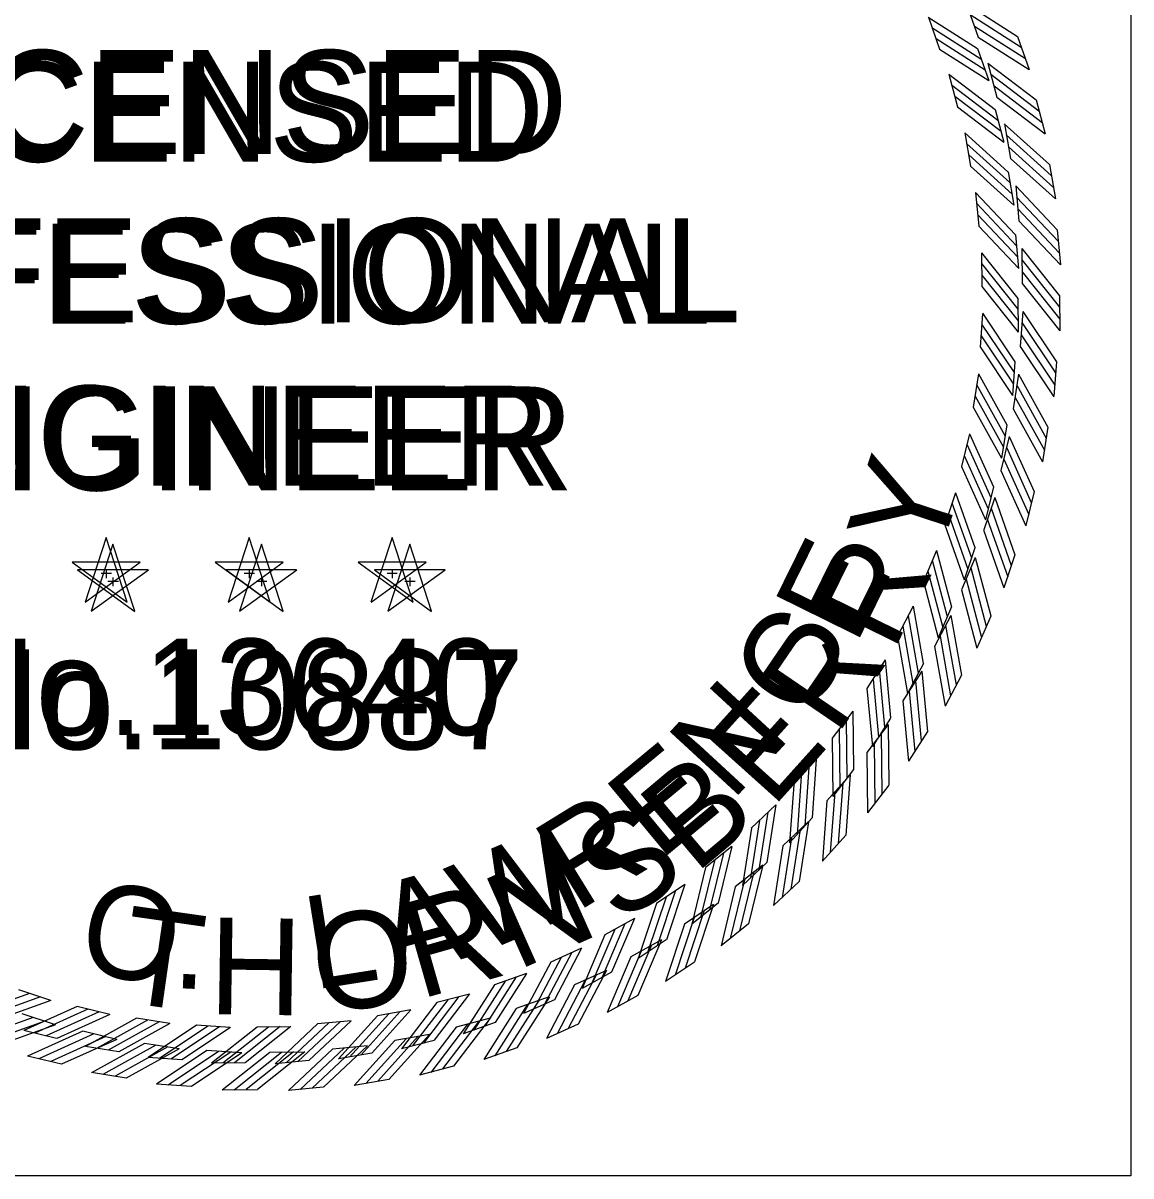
# Model space of a CAD drawing. Extents: x 0 to 1228740, y 0 to 152440.
# Drawn here: x 35.691 to 37.414, y 22.317 to 24.11 of the extents above; entities that cross this region are included whole.
import ezdxf

# ---------------------------------------------------------------- set-up
doc = ezdxf.new("R2010")
doc.units = 0
for name, color, linetype in [('R_No Plot', 7, 'Continuous'), ('STAMP', 7, 'Continuous'), ('STAMP_PP', 7, 'Continuous')]:
    doc.layers.add(name, color=color, linetype=linetype)

msp = doc.modelspace()

# ---------------------------------------------------------------- linework, layer by layer
at = {"layer": 'R_No Plot'}
msp.add_lwpolyline([(34.6722, 25.0583), (37.4139, 25.0583), (37.4139, 22.3166), (34.6722, 22.3166)], close=True, dxfattribs=at)
at = {"layer": 'STAMP'}
for p, q in [((37.0989, 24.1186), (37.1164, 24.0691)), ((37.1753, 24.0698), (37.1928, 24.0204)), ((37.1309, 24.0299), (37.1443, 23.9791)), ((37.203, 23.9749), (37.2164, 23.9243)), ((37.1555, 23.9389), (37.1646, 23.8872)), ((37.2228, 23.8782), (37.2319, 23.8266)), ((37.1724, 23.8462), (37.1773, 23.7939)), ((37.2345, 23.7801), (37.2393, 23.7279)), ((37.1817, 23.7524), (37.1822, 23.6998)), ((37.2381, 23.6814), (37.2386, 23.629)), ((37.1832, 23.6581), (37.1793, 23.6057)), ((37.2335, 23.5827), (37.2297, 23.5304)), ((37.1768, 23.564), (37.1687, 23.5122)), ((37.1628, 23.4708), (37.1503, 23.4198)), ((37.2208, 23.4847), (37.2126, 23.433)), ((37.2, 23.3882), (37.1876, 23.3372)), ((37.1411, 23.3791), (37.1245, 23.3293)), ((35.8206, 23.3094), (35.7878, 23.2088)), ((35.8532, 23.2089), (35.8206, 23.3095)), ((36.0429, 23.3094), (36.0101, 23.2088)), ((36.0755, 23.2089), (36.0429, 23.3095)), ((36.2651, 23.3094), (36.2323, 23.2088)), ((36.2978, 23.2089), (36.2652, 23.3095)), ((37.1714, 23.2936), (37.1548, 23.2439)), ((37.1118, 23.2895), (37.0912, 23.2412)), ((35.8734, 23.271), (35.7676, 23.2711)), ((35.7677, 23.271), (35.8533, 23.2087)), ((35.7879, 23.2089), (35.8736, 23.271)), ((35.8207, 23.2598), (35.8207, 23.2465)), ((36.0957, 23.271), (35.9899, 23.2711)), ((35.99, 23.271), (36.0755, 23.2087)), ((36.0102, 23.2089), (36.0958, 23.271)), ((36.043, 23.2598), (36.043, 23.2465)), ((36.318, 23.271), (36.2122, 23.2711)), ((36.2123, 23.271), (36.2978, 23.2087)), ((36.2325, 23.2089), (36.3181, 23.271)), ((36.2652, 23.2598), (36.2652, 23.2465)), ((35.813, 23.2541), (35.8288, 23.2541)), ((36.0353, 23.2541), (36.051, 23.2541)), ((36.2576, 23.2541), (36.2733, 23.2541)), ((37.0753, 23.2026), (37.0508, 23.1561)), ((37.135, 23.2018), (37.1144, 23.1536)), ((37.0318, 23.119), (37.0034, 23.0747)), ((37.0912, 23.1133), (37.0666, 23.067)), ((36.9814, 23.0393), (36.9496, 22.9975)), ((37.0402, 23.0287), (37.0119, 22.9845)), ((36.9247, 22.964), (36.8895, 22.925)), ((36.9823, 22.9486), (36.9505, 22.9069)), ((36.8619, 22.8936), (36.8236, 22.8577)), ((36.9181, 22.8735), (36.883, 22.8346)), ((36.7936, 22.8287), (36.7524, 22.7961)), ((36.8479, 22.804), (36.8097, 22.7682)), ((36.7201, 22.7697), (36.6764, 22.7405)), ((36.7722, 22.7406), (36.7312, 22.708)), ((36.642, 22.7169), (36.596, 22.6914)), ((36.6915, 22.6836), (36.6479, 22.6545)), ((36.5598, 22.6707), (36.5119, 22.6492)), ((36.4741, 22.6315), (36.4246, 22.614)), ((36.6064, 22.6335), (36.5606, 22.6081)), ((35.7346, 22.5894), (35.6848, 22.606)), ((36.3854, 22.5995), (36.3346, 22.5861)), ((35.8263, 22.5676), (35.7753, 22.5801)), ((36.2944, 22.5749), (36.2427, 22.5658)), ((36.5175, 22.5905), (36.4697, 22.569)), ((35.9195, 22.5536), (35.8676, 22.5617)), ((36.2017, 22.558), (36.1494, 22.5532)), ((35.7436, 22.5304), (35.6927, 22.5428)), ((36.0136, 22.5473), (35.9612, 22.5511)), ((36.1078, 22.5487), (36.0553, 22.5482)), ((36.4252, 22.5551), (36.3758, 22.5376)), ((36.3304, 22.5274), (36.2798, 22.5141)), ((35.8402, 22.5096), (35.7885, 22.5178)), ((36.2337, 22.5076), (36.182, 22.4985)), ((35.9382, 22.4969), (35.8859, 22.5007)), ((36.0369, 22.4923), (35.9845, 22.4918)), ((36.1356, 22.4959), (36.0834, 22.4911))]:
    msp.add_line(p, q, dxfattribs=at)
for points in [[(37.0988, 24.1186), (37.1753, 24.0698)], [(37.1043, 24.1027), (37.1807, 24.0539)], [(37.1108, 24.0857), (37.1872, 24.0368)], [(37.1164, 24.0691), (37.1928, 24.0203)], [(37.1308, 24.03), (37.203, 23.975)], [(37.135, 24.0136), (37.2071, 23.9587)], [(37.14, 23.9961), (37.2121, 23.9412)], [(37.1443, 23.9792), (37.2164, 23.9242)], [(37.1554, 23.939), (37.2227, 23.8782)], [(37.1582, 23.9223), (37.2255, 23.8616)], [(37.1617, 23.9045), (37.2291, 23.8437)], [(37.1646, 23.8872), (37.232, 23.8265)], [(37.1724, 23.8462), (37.2345, 23.7802)], [(37.1738, 23.8294), (37.2359, 23.7633)], [(37.1758, 23.8113), (37.2379, 23.7453)], [(37.1773, 23.7939), (37.2394, 23.7279)], [(37.1816, 23.7524), (37.2381, 23.6814)], [(37.1816, 23.7356), (37.2381, 23.6646)], [(37.1822, 23.7174), (37.2386, 23.6464)], [(37.1822, 23.6999), (37.2386, 23.6289)], [(37.1831, 23.6582), (37.2335, 23.5828)], [(37.1817, 23.6414), (37.2321, 23.566)], [(37.1808, 23.6232), (37.2311, 23.5478)], [(37.1793, 23.6058), (37.2297, 23.5304)], [(37.1768, 23.5641), (37.2208, 23.4848)], [(37.174, 23.5475), (37.218, 23.4682)], [(37.1716, 23.5294), (37.2156, 23.4501)], [(37.1687, 23.5122), (37.2127, 23.4329)], [(37.1627, 23.4709), (37.2, 23.3882)], [(37.1586, 23.4546), (37.1959, 23.3719)], [(37.1547, 23.4368), (37.1919, 23.3541)], [(37.1504, 23.4198), (37.1877, 23.3372)], [(37.1356, 23.3632), (37.1659, 23.2778)], [(37.141, 23.3792), (37.1713, 23.2937)], [(37.1302, 23.3458), (37.1605, 23.2604)], [(37.1245, 23.3293), (37.1548, 23.2439)], [(37.105, 23.2741), (37.1282, 23.1864)], [(37.1118, 23.2895), (37.135, 23.2019)], [(37.0983, 23.2572), (37.1214, 23.1695)], [(37.0912, 23.2412), (37.1144, 23.1536)], [(37.0753, 23.2026), (37.0911, 23.1134)], [(37.0673, 23.1878), (37.0831, 23.0985)], [(37.0591, 23.1715), (37.075, 23.0823)], [(37.0508, 23.1562), (37.0666, 23.0669)], [(37.0317, 23.119), (37.0402, 23.0288)], [(37.0225, 23.1049), (37.0309, 23.0146)], [(37.013, 23.0894), (37.0215, 22.9991)], [(37.0035, 23.0748), (37.0119, 22.9845)], [(36.9711, 23.026), (36.972, 22.9354)], [(36.9814, 23.0393), (36.9824, 22.9487)], [(36.9603, 23.0113), (36.9613, 22.9206)], [(36.9496, 22.9975), (36.9505, 22.9069)], [(36.9133, 22.9516), (36.9067, 22.8612)], [(36.9247, 22.964), (36.9181, 22.8736)], [(36.9014, 22.9379), (36.8948, 22.8474)], [(36.8896, 22.925), (36.883, 22.8346)], [(36.8495, 22.8823), (36.8355, 22.7927)], [(36.862, 22.8937), (36.8479, 22.8041)], [(36.8365, 22.8695), (36.8225, 22.78)], [(36.8237, 22.8577), (36.8097, 22.7681)], [(36.7936, 22.8288), (36.7722, 22.7407)], [(36.7803, 22.8184), (36.7589, 22.7303)], [(36.7525, 22.7961), (36.7311, 22.708)], [(36.7663, 22.8068), (36.7449, 22.7187)], [(36.706, 22.7605), (36.6774, 22.6744)], [(36.7201, 22.7697), (36.6916, 22.6837)], [(36.6765, 22.7405), (36.6479, 22.6545)], [(36.6911, 22.7501), (36.6625, 22.664)], [(36.6115, 22.6997), (36.5759, 22.6163)], [(36.6272, 22.7089), (36.5916, 22.6255)], [(36.642, 22.7169), (36.6065, 22.6335)], [(36.5961, 22.6914), (36.5605, 22.608)], [(36.5444, 22.664), (36.5021, 22.5838)], [(36.5598, 22.6708), (36.5175, 22.5906)], [(36.512, 22.6492), (36.4696, 22.569)], [(36.528, 22.6562), (36.4856, 22.576)], [(36.4741, 22.6316), (36.4253, 22.5552)], [(36.4246, 22.614), (36.3758, 22.5376)], [(36.4411, 22.6196), (36.3923, 22.5432)], [(36.4582, 22.6261), (36.4094, 22.5497)], [(35.7013, 22.6002), (35.6159, 22.5699)], [(35.7187, 22.5949), (35.6333, 22.5645)], [(36.3691, 22.5954), (36.3141, 22.5233)], [(36.3855, 22.5996), (36.3305, 22.5275)], [(35.7347, 22.5894), (35.6492, 22.5591)], [(35.7753, 22.58), (35.6927, 22.5428)], [(35.7923, 22.5757), (35.7096, 22.5385)], [(36.2944, 22.575), (36.2337, 22.5077)], [(36.3347, 22.5861), (36.2797, 22.514)], [(36.3516, 22.5904), (36.2966, 22.5183)], [(35.81, 22.5718), (35.7274, 22.5346)], [(35.8264, 22.5677), (35.7437, 22.5304)], [(35.8677, 22.5617), (35.7884, 22.5177)], [(35.8849, 22.5588), (35.8056, 22.5149)], [(35.903, 22.5564), (35.8237, 22.5124)], [(36.1849, 22.5566), (36.1188, 22.4946)], [(36.2017, 22.558), (36.1356, 22.4959)], [(36.2427, 22.5658), (36.182, 22.4985)], [(36.26, 22.5687), (36.1992, 22.5013)], [(36.2778, 22.5722), (36.2171, 22.5049)], [(35.9196, 22.5536), (35.8403, 22.5097)], [(35.9613, 22.5511), (35.8859, 22.5007)], [(35.9787, 22.5496), (35.9033, 22.4993)], [(35.9968, 22.5487), (35.9214, 22.4983)], [(36.0137, 22.5473), (35.9383, 22.4969)], [(36.0554, 22.5482), (35.9844, 22.4918)], [(36.0728, 22.5482), (36.0019, 22.4918)], [(36.091, 22.5488), (36.0201, 22.4924)], [(36.1079, 22.5488), (36.0369, 22.4924)], [(36.1494, 22.5531), (36.0833, 22.491)], [(36.1668, 22.5546), (36.1007, 22.4925)]]:
    msp.add_lwpolyline(points, dxfattribs=at)
at = {"layer": 'STAMP_PP'}
for p, q in [((37.1584, 24.1392), (37.1766, 24.0878)), ((37.2377, 24.0885), (37.2559, 24.0372)), ((37.1916, 24.0472), (37.2055, 23.9944)), ((37.2665, 23.9901), (37.2803, 23.9375)), ((37.2171, 23.9527), (37.2266, 23.899)), ((37.287, 23.8896), (37.2965, 23.836)), ((37.2347, 23.8564), (37.2397, 23.8021)), ((37.2992, 23.7878), (37.3042, 23.7336)), ((37.2443, 23.759), (37.2448, 23.7045)), ((37.3029, 23.6853), (37.3034, 23.6309)), ((37.2459, 23.6611), (37.2418, 23.6067)), ((37.2981, 23.5828), (37.2941, 23.5286)), ((37.2393, 23.5635), (37.2308, 23.5096)), ((37.2849, 23.4811), (37.2765, 23.4274)), ((37.2247, 23.4667), (37.2118, 23.4137)), ((37.2021, 23.3715), (37.1849, 23.3197)), ((37.2634, 23.3809), (37.2505, 23.328)), ((35.8311, 23.2991), (35.7971, 23.1947)), ((35.8651, 23.1947), (35.8312, 23.2992)), ((36.0619, 23.2991), (36.0279, 23.1947)), ((36.0958, 23.1947), (36.062, 23.2992)), ((36.2927, 23.2991), (36.2587, 23.1947)), ((36.3266, 23.1947), (36.2928, 23.2992)), ((37.1718, 23.2784), (37.1504, 23.2283)), ((37.2336, 23.2827), (37.2164, 23.2311)), ((35.886, 23.2592), (35.7762, 23.2593)), ((35.7763, 23.2592), (35.8651, 23.1946)), ((35.7972, 23.1947), (35.8862, 23.2592)), ((36.1168, 23.2592), (36.007, 23.2593)), ((36.0071, 23.2592), (36.0959, 23.1946)), ((36.028, 23.1947), (36.1169, 23.2592)), ((36.3476, 23.2592), (36.2377, 23.2593)), ((36.2378, 23.2592), (36.3266, 23.1946)), ((36.2588, 23.1947), (36.3477, 23.2592)), ((35.8233, 23.2417), (35.8397, 23.2417)), ((35.8312, 23.2475), (35.8312, 23.2338)), ((36.0541, 23.2417), (36.0704, 23.2417)), ((36.062, 23.2475), (36.062, 23.2338)), ((36.2849, 23.2417), (36.3012, 23.2417)), ((36.2928, 23.2475), (36.2928, 23.2338)), ((37.1339, 23.1882), (37.1084, 23.14)), ((37.1958, 23.1874), (37.1744, 23.1373)), ((37.0887, 23.1014), (37.0593, 23.0554)), ((37.1503, 23.0955), (37.1249, 23.0474)), ((37.0364, 23.0186), (37.0033, 22.9753)), ((37.0974, 23.0076), (37.068, 22.9618)), ((36.9775, 22.9404), (36.9409, 22.9)), ((37.0374, 22.9245), (37.0043, 22.8812)), ((36.9123, 22.8674), (36.8726, 22.8301)), ((36.9707, 22.8465), (36.9342, 22.8062)), ((36.8414, 22.8), (36.7987, 22.7661)), ((36.8978, 22.7744), (36.8581, 22.7372)), ((36.7651, 22.7387), (36.7197, 22.7084)), ((36.8192, 22.7085), (36.7766, 22.6747)), ((36.684, 22.6839), (36.6363, 22.6575)), ((36.7354, 22.6493), (36.6901, 22.6192)), ((36.5987, 22.636), (36.5489, 22.6136)), ((36.5096, 22.5953), (36.4582, 22.5771)), ((36.647, 22.5973), (36.5994, 22.571)), ((35.7419, 22.5515), (35.6901, 22.5687)), ((36.4176, 22.562), (36.3648, 22.5482)), ((35.8371, 22.529), (35.7841, 22.5419)), ((36.5547, 22.5527), (36.5051, 22.5304)), ((35.9339, 22.5144), (35.88, 22.5228)), ((36.3231, 22.5365), (36.2694, 22.5271)), ((35.7513, 22.4903), (35.6984, 22.5031)), ((36.0315, 22.5078), (35.9772, 22.5118)), ((36.1294, 22.5093), (36.0749, 22.5088)), ((36.2268, 22.5189), (36.1725, 22.5139)), ((36.459, 22.5159), (36.4077, 22.4978)), ((36.3605, 22.4872), (36.3079, 22.4733)), ((35.8515, 22.4687), (35.7978, 22.4772)), ((36.26, 22.4666), (36.2064, 22.4572)), ((35.9532, 22.4555), (35.899, 22.4595)), ((36.0557, 22.4507), (36.0013, 22.4502)), ((36.1582, 22.4545), (36.104, 22.4495))]:
    msp.add_line(p, q, dxfattribs=at)
for points in [[(37.1583, 24.1393), (37.2376, 24.0886)], [(37.164, 24.1227), (37.2433, 24.072)], [(37.1707, 24.105), (37.25, 24.0544)], [(37.1766, 24.0879), (37.2559, 24.0372)], [(37.1915, 24.0472), (37.2664, 23.9902)], [(37.1958, 24.0302), (37.2707, 23.9732)], [(37.2011, 24.0121), (37.2759, 23.955)], [(37.2055, 23.9945), (37.2804, 23.9374)], [(37.217, 23.9527), (37.287, 23.8897)], [(37.2199, 23.9355), (37.2898, 23.8724)], [(37.2236, 23.9169), (37.2935, 23.8539)], [(37.2266, 23.899), (37.2965, 23.836)], [(37.2347, 23.8565), (37.2991, 23.7879)], [(37.2361, 23.839), (37.3006, 23.7704)], [(37.2383, 23.8202), (37.3027, 23.7516)], [(37.2398, 23.8022), (37.3042, 23.7336)], [(37.2443, 23.7591), (37.3028, 23.6854)], [(37.2443, 23.7415), (37.3028, 23.6679)], [(37.2449, 23.7227), (37.3034, 23.649)], [(37.2449, 23.7045), (37.3034, 23.6308)], [(37.2458, 23.6612), (37.2981, 23.5829)], [(37.2444, 23.6437), (37.2966, 23.5655)], [(37.2434, 23.6249), (37.2957, 23.5466)], [(37.2419, 23.6068), (37.2942, 23.5285)], [(37.2392, 23.5635), (37.2849, 23.4812)], [(37.2364, 23.5463), (37.282, 23.4639)], [(37.2338, 23.5275), (37.2795, 23.4452)], [(37.2309, 23.5097), (37.2765, 23.4273)], [(37.2247, 23.4668), (37.2633, 23.381)], [(37.2204, 23.4498), (37.259, 23.364)], [(37.2163, 23.4313), (37.255, 23.3455)], [(37.2118, 23.4138), (37.2505, 23.3279)], [(37.2021, 23.3715), (37.2336, 23.2828)], [(37.1964, 23.355), (37.2279, 23.2662)], [(37.1909, 23.3369), (37.2223, 23.2482)], [(37.185, 23.3198), (37.2164, 23.231)], [(37.1718, 23.2785), (37.1958, 23.1875)], [(37.1648, 23.2624), (37.1888, 23.1714)], [(37.1577, 23.2449), (37.1817, 23.1539)], [(37.1504, 23.2283), (37.1745, 23.1373)], [(37.1339, 23.1882), (37.1503, 23.0956)], [(37.1255, 23.1728), (37.142, 23.0802)], [(37.1171, 23.1559), (37.1335, 23.0633)], [(37.1084, 23.14), (37.1249, 23.0473)], [(37.0887, 23.1015), (37.0974, 23.0077)], [(37.0791, 23.0868), (37.0878, 22.9931)], [(37.0692, 23.0707), (37.078, 22.9769)], [(37.0593, 23.0555), (37.0681, 22.9617)], [(37.0257, 23.0049), (37.0266, 22.9107)], [(37.0364, 23.0187), (37.0374, 22.9246)], [(37.0145, 22.9896), (37.0155, 22.8955)], [(37.0034, 22.9753), (37.0043, 22.8812)], [(36.9775, 22.9405), (36.9707, 22.8466)], [(36.9657, 22.9276), (36.9588, 22.8337)], [(36.941, 22.9), (36.9342, 22.8061)], [(36.9533, 22.9133), (36.9465, 22.8194)], [(36.9124, 22.8675), (36.8978, 22.7745)], [(36.8995, 22.8556), (36.8849, 22.7626)], [(36.8726, 22.8301), (36.8581, 22.7371)], [(36.886, 22.8424), (36.8714, 22.7494)], [(36.8276, 22.7893), (36.8054, 22.6978)], [(36.8414, 22.8001), (36.8192, 22.7086)], [(36.813, 22.7773), (36.7909, 22.6858)], [(36.7987, 22.7661), (36.7766, 22.6746)], [(36.7651, 22.7388), (36.7355, 22.6494)], [(36.735, 22.7184), (36.7053, 22.629)], [(36.7505, 22.7292), (36.7208, 22.6398)], [(36.7198, 22.7084), (36.6901, 22.6191)], [(36.684, 22.684), (36.6471, 22.5974)], [(36.6523, 22.6661), (36.6154, 22.5795)], [(36.6686, 22.6756), (36.6317, 22.589)], [(36.6364, 22.6575), (36.5994, 22.5709)], [(36.5827, 22.629), (36.5387, 22.5458)], [(36.5987, 22.636), (36.5547, 22.5528)], [(36.549, 22.6136), (36.505, 22.5303)], [(36.5656, 22.6209), (36.5216, 22.5376)], [(36.5097, 22.5953), (36.459, 22.516)], [(36.4583, 22.5771), (36.4076, 22.4977)], [(36.4754, 22.5829), (36.4248, 22.5036)], [(36.4931, 22.5896), (36.4424, 22.5103)], [(35.7073, 22.5628), (35.6186, 22.5313)], [(35.7254, 22.5572), (35.6367, 22.5257)], [(36.4007, 22.5578), (36.3436, 22.4829)], [(36.4176, 22.5621), (36.3606, 22.4872)], [(35.7419, 22.5515), (35.6532, 22.5201)], [(35.7842, 22.5418), (35.6984, 22.5031)], [(36.3649, 22.5481), (36.3079, 22.4733)], [(36.3825, 22.5526), (36.3254, 22.4777)], [(35.8017, 22.5374), (35.7159, 22.4987)], [(35.8202, 22.5333), (35.7344, 22.4946)], [(35.8372, 22.529), (35.7514, 22.4903)], [(35.8801, 22.5228), (35.7977, 22.4771)], [(36.2695, 22.527), (36.2064, 22.4571)], [(36.2873, 22.53), (36.2243, 22.4601)], [(36.3059, 22.5337), (36.2428, 22.4638)], [(36.3231, 22.5366), (36.2601, 22.4667)], [(35.898, 22.5198), (35.8156, 22.4742)], [(35.9167, 22.5173), (35.8344, 22.4716)], [(35.934, 22.5144), (35.8516, 22.4687)], [(35.9772, 22.5118), (35.8989, 22.4595)], [(35.9953, 22.5103), (35.917, 22.458)], [(36.0142, 22.5093), (35.9359, 22.457)], [(36.0316, 22.5078), (35.9533, 22.4556)], [(36.0749, 22.5088), (36.0012, 22.4502)], [(36.0931, 22.5088), (36.0194, 22.4502)], [(36.112, 22.5094), (36.0383, 22.4508)], [(36.1295, 22.5094), (36.0558, 22.4508)], [(36.1726, 22.5139), (36.104, 22.4494)], [(36.1906, 22.5154), (36.122, 22.4509)], [(36.2094, 22.5175), (36.1408, 22.4531)], [(36.2269, 22.519), (36.1583, 22.4545)]]:
    msp.add_lwpolyline(points, dxfattribs=at)

# ---------------------------------------------------------------- texts
at = {"layer": 'STAMP'}
for s, height, p in [('LICENSED', 0.15559, (35.461, 23.8938)), ('PROFESSIONAL', 0.155594, (35.1424, 23.6419)), ('ENGINEER', 0.15559, (35.4239, 23.39)), ('No.13640', 0.15004, (35.5662, 23.0021))]:
    msp.add_text(s, height=height, dxfattribs=at).set_placement(p)
for s, rotation, p in [('E', 63.7362, (36.9856, 23.1401)), ('C', 56.0754, (36.9043, 23.02)), ('N', 47.3202, (36.7927, 22.8975)), ('E', 39.6594, (36.6808, 22.8052)), ('R', 31.6338, (36.5514, 22.7255)), ('W', 22.8786, (36.3992, 22.6601)), ('O', 349.3169, (35.7728, 22.6372)), ('A', 15.5826, (36.2659, 22.6238)), ('L', 9.0162, (36.1428, 22.6059)), ('.', 357.3425, (35.9221, 22.6091))]:
    msp.add_text(s, height=0.1448, rotation=rotation, dxfattribs=at).set_placement(p)
at = {"layer": 'STAMP_PP'}
for s, height, p in [('LICENSED', 0.16155, (35.4578, 23.9059)), ('PROFESSIONAL', 0.161547, (35.127, 23.6443)), ('ENGINEER', 0.16155, (35.4193, 23.3828)), ('No.10887', 0.15578, (35.567, 22.98))]:
    msp.add_text(s, height=height, dxfattribs=at).set_placement(p)
for s, rotation, p in [('Y', 71.7733, (37.1128, 23.2718)), ('R', 63.7477, (37.044, 23.1299)), ('R', 55.7221, (36.956, 22.9991)), ('E', 48.0613, (36.8558, 22.8868)), ('B', 40.0357, (36.7357, 22.7846)), ('S', 32.7397, (36.6152, 22.707)), ('N', 23.9845, (36.4589, 22.6351)), ('R', 15.9589, (36.3076, 22.5908)), ('T', 351.882, (35.8377, 22.5885)), ('H', 359.178, (35.9796, 22.5683)), ('O', 7.9332, (36.1516, 22.568))]:
    msp.add_text(s, height=0.1503, rotation=rotation, dxfattribs=at).set_placement(p)

doc.saveas('drawing.dxf')
